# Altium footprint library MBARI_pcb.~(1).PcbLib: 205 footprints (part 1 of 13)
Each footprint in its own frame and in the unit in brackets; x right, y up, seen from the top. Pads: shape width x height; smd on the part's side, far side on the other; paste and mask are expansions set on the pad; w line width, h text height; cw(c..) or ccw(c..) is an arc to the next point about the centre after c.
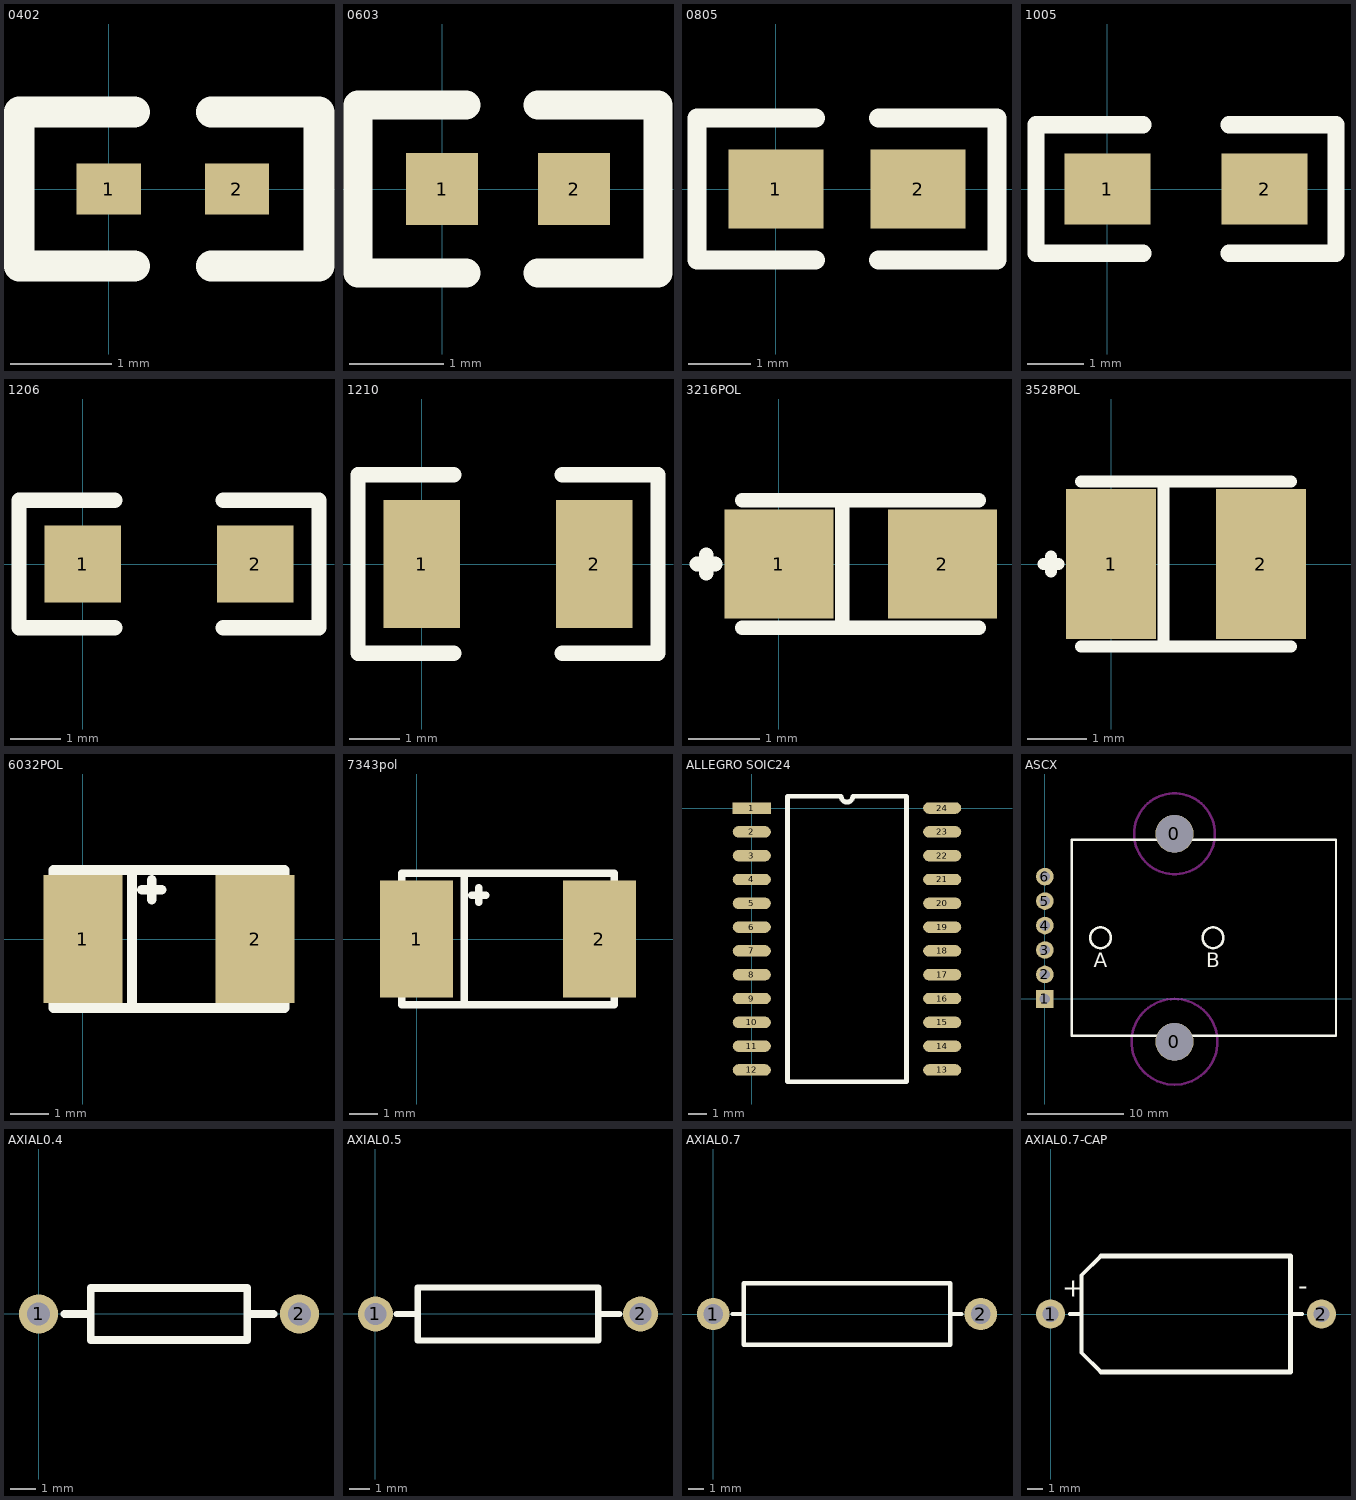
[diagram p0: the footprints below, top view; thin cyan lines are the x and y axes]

## 0402 [mil]
pads (2):
  rect 25x20 smd: 1(0,0) 2(50,0)
TopOverlay:
  lines w12: 10,-30 -35,-30 -35,30 10,30 ; 40,-30 82,-30 82,30 40,30

## 0603 [mil]
pads (2):
  rect 30x30 smd: 1(0,0) 2(55,0)
TopOverlay:
  lines w12: 10,-35 -35,-35 -35,35 10,35 ; 40,-35 90,-35 90,35 40,35

## 0805 [mil]
pads (2):
  rect 60x50 smd: 1(0,0) 2(90,0)
TopOverlay:
  lines w12: 25,-45 -50,-45 -50,45 25,45 ; 65,-45 140,-45 140,45 65,45

## 1005 [mil]
pads (2):
  rect 60x50 smd: 1(0,0) 2(110,0)
TopOverlay:
  lines w12: 25,-45 -50,-45 -50,45 25,45 ; 85,-45 160,-45 160,45 85,45

## 1206 [mil]
pads (2):
  rect 60x60 smd: 1(0,0) 2(135,0)
TopOverlay:
  lines w12: 25,-50 -50,-50 -50,50 25,50 ; 110,-50 185,-50 185,50 110,50

## 1210 [mil]
pads (2):
  rect 60x100 smd: 1(0,0) 2(135,0)
TopOverlay:
  lines w12: 25,-70 -50,-70 -50,70 25,70 ; 110,-70 185,-70 185,70 110,70

## 3216POL [mil] "Polarized Cap EIA-3216-18, similiar to1206 footprint"
height 63
pads (2):
  rect 60x60 smd: 1(0,0) 2(90,0)
TopOverlay:
  lines w8: -45,0 -35,0 ; -40,-5 -40,5 ; -20,-35 110,-35 ; -20,35 110,35 ; 35,-35 35,35

## 3528POL [mil] "Polarized chip capacitor EIA 3528-21"
height 75
pads (2):
  rect 60x100 smd: 1(0,0) 2(100,0)
TopOverlay:
  lines w8: -45,0 -35,0 ; -40,-5 -40,5 ; -20,-55 120,-55 ; -20,55 120,55 ; 35,-55 35,55

## 6032POL [mil] "Polarized chip cap EIA 6032-28"
height 98
pads (2):
  rect 80x130 smd: 1(0,0) 2(175,0)
TopOverlay:
  lines w10: -30,-65 -30,-70 205,-70 205,-65 ; -30,65 -30,70 205,70 205,65 ; 50,-70 50,70 ; 60,50 80,50 ; 70,40 70,60

## 7343pol [mil] "Polarized chip cap EIA 7343-31"
height 110
pads (2):
  rect 100x160 smd: 1(0,0) 2(250,0)
TopOverlay:
  lines w10: -20,-80 -20,-90 270,-90 270,-80 ; -20,80 -20,90 270,90 270,80 ; 65,-90 65,90 ; 75,60 95,60 ; 85,50 85,70

## ALLEGRO SOIC24 [mil]
pads (24):
  rect 80x24 smd: 1(0,0)
  oval 80x24 smd: 2(0,-50) 3(0,-100) 4(0,-150) 5(0,-200) 6(0,-250) 7(0,-300) 8(0,-350) 9(0,-400) 10(0,-450) 11(0,-500) 12(0,-550) 13(400,-550) 14(400,-500) 15(400,-450) 16(400,-400) 17(400,-350) 18(400,-300) 19(400,-250) 20(400,-200) 21(400,-150) 22(400,-100) 23(400,-50) 24(400,0)
TopOverlay:
  lines w10: 75,-575 75,25 187.5,25 ccw(c200,25) 212.5,25 325,25 325,-575 75,-575

## ASCX [mil]
pads (8):
  round 155 hole 152: 0(530,-175) 0(530,675)
  rect 72x72 hole 42: 1(0,0)
  round 72 hole 42: 2(0,100) 3(0,200) 4(0,300) 5(0,400) 6(0,500)
TopOverlay:
  circle w10: c227.57,250 r42.43
  circle w10: c687.57,250 r42.43
  lines w10: 110,-150 110,650 1190,650 1190,-150 110,-150
  text "A" at 200,130 h60
  text "B" at 660,130 h60
KeepOutLayer:
  circle w10: c530,675 r165.3
  circle w10: c530,-175 r175.29

## AXIAL0.4 [mil]
pads (2):
  round 60 hole 35: 1(0,0) 2(400,0)
TopOverlay:
  lines w12: 40,-0.04 80,-0.04 ; 320,-0.04 360,-0.04 ; 80,-40.04 320,-40.04 320,39.96 80,39.96 80,-40.04

## AXIAL0.5 [mil]
pads (2):
  round 66 hole 42: 1(0,0) 2(500,0)
TopOverlay:
  lines w12: 40,-0.04 80,-0.04 ; 420,-0.04 460,-0.04 ; 80,-50.04 80,49.96 420,49.96 420,-50.04 80,-50.04

## AXIAL0.7 [mil]
pads (2):
  round 85 hole 52: 1(0,0) 2(700,0)
TopOverlay:
  lines w10: 50,0 80,0 ; 620,0 650,0
  lines w12: 80,-80 620,-80 620,80 80,80 80,-80

## AXIAL0.7-CAP [mil]
pads (2):
  round 75 hole 42: 1(0,0) 2(700,0)
TopOverlay:
  lines w10: 50,0 80,0 ; 130,-150 80,-100 80,0 ; 130,150 80,100 80,0 ; 620,0 650,0
  lines w12: 130,-150 620,-150 620,150 130,150
  text "+" at 30,45 h50
  text "-" at 640,50 h50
